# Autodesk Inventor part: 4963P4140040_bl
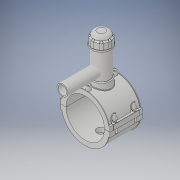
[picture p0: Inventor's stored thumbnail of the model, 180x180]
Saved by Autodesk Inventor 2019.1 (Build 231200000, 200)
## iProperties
Created: 2017-07
Part Number: 4963P4140040_bl
Material: Generic
Document SubType Name: Modeling
Designer: KIM
Density: 1 g/cm^3
Appearance: Default
Author: KIM
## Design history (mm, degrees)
derived "4963P4.ipt"
feature "Solid1::4963P4.ipt" dims "ScaleForDerivedMember" = 10
feature "Solid2::4963P4.ipt" dims "ScaleForDerivedMember" = 10
feature "Solid3::4963P4.ipt" dims "ScaleForDerivedMember" = 10
tag "TaggingFeature1"
body "Solid1"
body "Solid2"
body "Solid3"
other parameters: "d3" = 35 [user parameter], "d4" = 118 [user parameter], "d5" = 0 [user parameter], "d6" = 0.1 [user parameter], "d8" = 0 [user parameter], "d19" = 6 [user parameter], "d20" = 6 [user parameter], "d21" = 70.8 [user parameter], "d23" = 0 [user parameter], "d24" = 35.4 [user parameter], "d26" = 0 [user parameter], "d27" = 3 [user parameter], "d28" = 3 [user parameter], "d29" = 3 [user parameter], "d30" = 46.66667 [user parameter], "d31" = 6 [user parameter], "d32" = 0 [user parameter], "d33" = 0 [user parameter], "d34" = 0.6 [user parameter], "d40" = 88.816 [user parameter], "d43" = 0 [user parameter], "d45" = 0 [user parameter], "d47" = 156.2 [user parameter], "d70" = 15 [user parameter], "d72" = 0 [user parameter], "d73" = 6 [user parameter], "d75" = 5 [user parameter], "d76" = 0 [user parameter], "d77" = 7 [user parameter], "d79" = 15 [user parameter], "d80" = 47.2 [user parameter], "d82" = 5 deg [user parameter], "d84" = 4 [user parameter], "d85" = 14 [user parameter], "d86" = 0 [user parameter], "d87" = 3 [user parameter], "d88" = 0 [user parameter], "d89" = 1 [user parameter], "d90" = 1 [user parameter], "d91" = 94.4 [user parameter], "d92" = 0 [user parameter], "d93" = 0.5 [user parameter], "d94" = 73.68421 [user parameter], "d96" = 174.216 [user parameter], "d97" = 2.36 [user parameter], "d98" = 0 [user parameter], "d102" = 1.4 [user parameter], "d120" = 140 deg [user parameter], "d121" = 24.228 [user parameter], "d122" = 20 deg [user parameter], "d123" = 341.6 [user parameter], "d124" = 102.48 [user parameter], "d126" = 0 [user parameter], "d143" = 144.2 [user parameter], "d145" = 23.69231 [user parameter], "d149" = 2.1 [user parameter], "d150" = 26.06154 [user parameter], "d153" = 118 [user parameter], "d154" = 0 [user parameter], "d156" = 85.4 [user parameter], "d157" = 160 deg [user parameter], "d159" = 6.16 [user parameter], "d161" = 2.1 [user parameter], "d162" = 70.8 [user parameter], "d163" = 0 [user parameter], "d167" = 14 [user parameter], "d168" = 83.31707 [user parameter], "d170" = 3.75 [user parameter], "d172" = 0 [user parameter], "d173" = 1 [user parameter], "d176" = 20 deg [user parameter], "d177" = 9.8 [user parameter], "d178" = 30.8 [user parameter], "d180" = 0 [user parameter], "d183" = 12.32 [user parameter], "d184" = 7.84 [user parameter], "d185" = 38.35 [user parameter], "d186" = 38.35 [user parameter], "d187" = 85.4 [user parameter], "d188" = 9.24 [user parameter], "d189" = 9.8 [user parameter], "d190" = 0 [user parameter], "d191" = 128.1 [user parameter], "d193" = 8 [user parameter], "d194" = 4.13 [user parameter], "d195" = 90 deg [user parameter], "d197" = 0 [user parameter], "d199" = 0 [user parameter], "d200" = 15.4 [user parameter], "d202" = 0 [user parameter], "d203" = 177 [user parameter], "d204" = 66.5 [user parameter], "d205" = 49 [user parameter], "d206" = 59.5 [user parameter], "d207" = 132.75 [user parameter], "d208" = 138.06 [user parameter], "d209" = 164.61 [user parameter], "d210" = 60.2 [user parameter], "d212" = 56 [user parameter], "d213" = 36 [user parameter], "d216" = 0 [user parameter], "d217" = 14 [user parameter], "d218" = 14 [user parameter], "d219" = 2.8 [user parameter], "d224" = 0 [user parameter], "d227" = 32 [user parameter], "d228" = 142 [user parameter], "d230" = 5.6 [user parameter], "L_" = 118 [user parameter], "d_t" = 6 [user parameter], "H_2" = 177 [user parameter], "H_" = 142 [user parameter], "d1" = 170.8 [user parameter], "d148" = 2.1 [user parameter], "d160" = 2.1 [user parameter], "d169" = 3.75 [user parameter], "d192" = 8 [user parameter]
